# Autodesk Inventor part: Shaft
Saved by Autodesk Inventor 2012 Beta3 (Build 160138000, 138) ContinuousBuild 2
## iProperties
Created: 2010-12
Part Number: Shaft
Material: Steel
Document SubType Name: Modeling
Designer: Thom Tremblay
Density: 1 g/cm^3
CustomPartVersion: 1
Author: Thom Tremblay
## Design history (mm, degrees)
sketch "Main Sketch"
  geometry: L1 (0, 0)-(51, 0) reference; L2 (0, 0)-(0, 5); L3 (26, 6)-(26, 12.5); L4 (0, 5)-(10, 5); L5 (41, 6)-(41, 5); L6 (38, 6)-(41, 6); L7 (51, 5)-(51, 0); L8 (41, 5)-(51, 5); L9 (38, 12.5)-(38, 6); L10 (26, 12.5)-(38, 12.5); L11 (10, 5)-(10, 6); L12 (10, 6)-(26, 6)
  constraints: 24 end point, 6 vertical, 2 horizontal
  dimensions: "d3" = 10 diameter of L4 L1 (derived); "d4" = 12 diameter of L6 L1 (derived); "d5" = 10 diameter of L8 L1 (derived); "d13" = 25 diameter of L10 L1 (derived); "d14" = 12 diameter of L12 L1 (derived)
revolve "Revolution1" sketch "Main Sketch" stored, may be unused: angle "d6" = 0 deg
chamfer "Chamfer4" distance "d18" = 0.5; stored, may be unused: second distance "d19" = 0.125, angle "d20" = 45 deg
chamfer "Chamfer2" distance "d10" = 0.5; stored, may be unused: second distance "d11" = 0.125, angle "d12" = 45 deg
node "Spur Gear Teeth1"
node "Keyway1"
body "Solid1"
feature "Spur Gear1"
feature "Shaft Keyway"
other parameters: "d0" = 0, "d1" = 0, "d2" = 0
